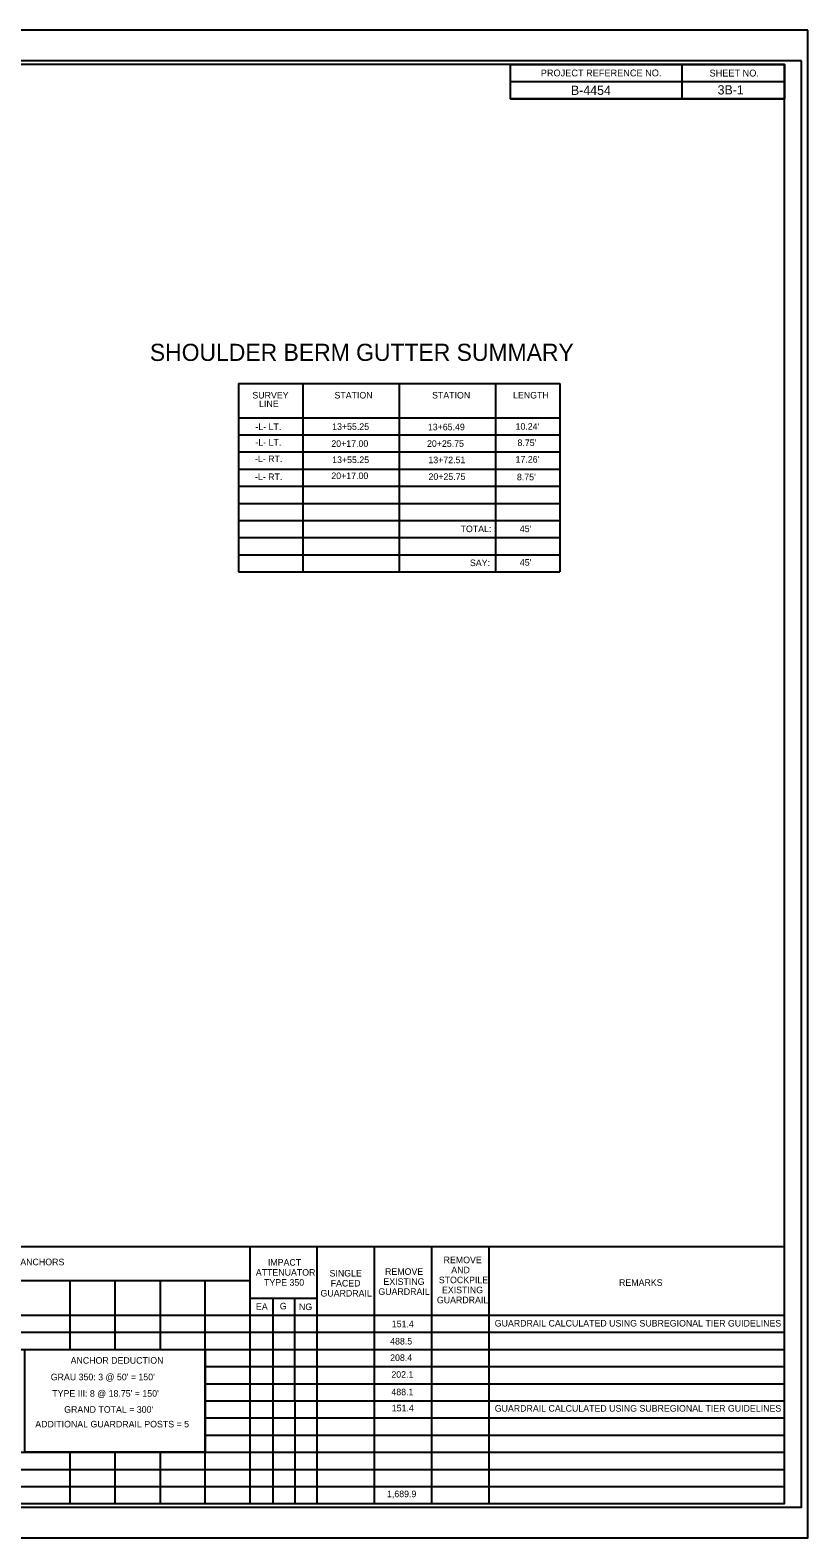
# Model space of a CAD drawing. Extents: x 1728103 to 1731948, y 539631 to 540733.
# Drawn here: x 1731380 to 1731948, y 539631 to 540731 of the extents above; entities that cross this region are included whole.
import ezdxf

# ---------------------------------------------------------------- set-up
doc = ezdxf.new("R2010")
doc.units = 0
for name, color, linetype in [('Sheet Cutting Line CELL', 7, 'Continuous'), ('Sheet Data Field CELL', 7, 'Continuous'), ('Sheet Plot Border Inside CELL', 7, 'Continuous'), ('Sheet Plot Border Outside CELL', 7, 'Continuous'), ('Sheet Summary Combination CELL', 7, 'Continuous'), ('Sheet Summary Combination Grid CELL', 7, 'Continuous')]:
    doc.layers.add(name, color=color, linetype=linetype)

msp = doc.modelspace()

# ---------------------------------------------------------------- linework, layer by layer
at = {"layer": 'Sheet Cutting Line CELL'}
for p, q in [((1731947.7, 540730.8), (1730263.7, 540730.8)), ((1730263.7, 539630.8), (1731947.7, 539630.8))]:
    msp.add_line(p, q, dxfattribs=at)
at = {"layer": 'Sheet Plot Border Inside CELL'}
msp.add_lwpolyline([(1731943.2, 540708.4), (1730276.7, 540708.4), (1730276.7, 539653.3), (1731943.2, 539653.3)], close=True, dxfattribs=at)
at = {"layer": 'Sheet Plot Border Outside CELL'}
msp.add_lwpolyline([(1731947.7, 540730.8), (1730263.7, 540730.8), (1730263.7, 539630.8), (1731947.7, 539630.8)], close=True, dxfattribs=at)
at = {"layer": 'Sheet Summary Combination CELL'}
for p, q in [((1731855.7, 540705.8), (1731855.7, 540680.8)), ((1731730.7, 540693.3), (1731930.7, 540693.3)), ((1731730.7, 540680.8), (1731930.7, 540680.8)), ((1731673.6, 540473.1), (1731673.6, 540473.1)), ((1731679.9, 540473), (1731679.9, 540473)), ((1731688.9, 540473.2), (1731688.9, 540473.2)), ((1731694.5, 540473.1), (1731694.5, 540473.1))]:
    msp.add_line(p, q, dxfattribs=at)
for points in [[(1731930.7, 540705.8), (1730430.7, 540705.8), (1730430.7, 539655.8), (1731930.7, 539655.8)], [(1731730.7, 540705.8), (1731930.7, 540705.8), (1731930.7, 540680.8), (1731730.7, 540680.8)]]:
    msp.add_lwpolyline(points, close=True, dxfattribs=at)
at = {"layer": 'Sheet Summary Combination Grid CELL'}
for p, q in [((1731532.4, 540473.1), (1731766.8, 540473.1)), ((1731532.4, 540473.1), (1731532.4, 540335.6)), ((1731579.3, 540473.1), (1731579.3, 540335.6)), ((1731649.6, 540473.1), (1731649.6, 540335.6)), ((1731719.9, 540473.1), (1731719.9, 540335.6)), ((1731766.8, 540473.1), (1731766.8, 540335.6)), ((1731532.4, 540448.1), (1731766.8, 540448.1)), ((1731532.4, 540435.6), (1731766.8, 540435.6)), ((1731532.4, 540423.1), (1731766.8, 540423.1)), ((1731532.4, 540410.6), (1731766.8, 540410.6)), ((1731532.4, 540398.1), (1731766.8, 540398.1)), ((1731532.4, 540385.6), (1731766.8, 540385.6)), ((1731532.4, 540373.1), (1731766.8, 540373.1)), ((1731532.4, 540360.6), (1731766.8, 540360.6)), ((1731532.4, 540348.1), (1731766.8, 540348.1)), ((1731532.4, 540335.6), (1731766.8, 540335.6)), ((1730430.7, 539843.3), (1731930.7, 539843.3)), ((1731540.7, 539843.3), (1731540.7, 539655.8)), ((1731589.5, 539843.3), (1731589.5, 539655.8)), ((1731631.3, 539843.3), (1731631.3, 539655.8)), ((1731673.1, 539843.3), (1731673.1, 539655.8)), ((1731715, 539843.3), (1731715, 539655.8)), ((1731540.7, 539818.3), (1731063.5, 539818.3)), ((1731409.4, 539818.3), (1731409.4, 539768.3)), ((1731442.2, 539818.3), (1731442.2, 539768.3)), ((1731475.1, 539818.3), (1731475.1, 539768.3)), ((1731507.9, 539818.3), (1731507.9, 539655.8)), ((1731540.7, 539805.6), (1731589.3, 539805.6)), ((1731557.3, 539805.6), (1731557.4, 539655.8)), ((1731573.3, 539805.6), (1731573.4, 539655.8)), ((1730430.7, 539793.3), (1731930.7, 539793.3)), ((1730430.7, 539780.8), (1731930.7, 539780.8)), ((1730430.7, 539768.3), (1731930.7, 539768.3)), ((1731507.9, 539755.8), (1731930.7, 539755.8)), ((1731507.9, 539743.3), (1731930.7, 539743.3)), ((1731507.9, 539730.8), (1731930.7, 539730.8)), ((1731507.9, 539718.3), (1731930.7, 539718.3)), ((1731507.9, 539705.8), (1731930.7, 539705.8)), ((1730430.7, 539693.3), (1731930.7, 539693.3)), ((1731409.4, 539693.3), (1731409.4, 539655.8)), ((1731442.2, 539693.3), (1731442.2, 539655.8)), ((1731475.1, 539693.3), (1731475.1, 539655.8)), ((1730430.7, 539680.8), (1731930.7, 539680.8)), ((1730430.7, 539668.3), (1731930.7, 539668.3))]:
    msp.add_line(p, q, dxfattribs=at)
msp.add_lwpolyline([(1731376.6, 539768.3), (1731508, 539768.3), (1731508, 539693.3), (1731376.6, 539693.3)], close=True, dxfattribs=at)

# ---------------------------------------------------------------- texts
at = {"layer": 'Sheet Data Field CELL'}
for s, p in [('B-4454', (1731774.9, 540683.6)), ('3B-1', (1731881.9, 540683.9))]:
    msp.add_text(s, height=6.75, dxfattribs=at).set_placement(p)
at = {"layer": 'Sheet Summary Combination CELL'}
for s, height, p in [('PROJECT REFERENCE NO.', 5, (1731752.9, 540697.1)), ('SHEET NO.', 5, (1731876, 540697)), ('SURVEY', 4.8, (1731542.5, 540462.1)), ('STATION', 4.8, (1731602.4, 540462.1)), ('STATION', 4.8, (1731673.6, 540462.1)), ('LENGTH', 4.8, (1731732.7, 540462.1)), ('LINE', 4.8, (1731547.4, 540455.8)), ('-L- LT.', 4.8, (1731544.7, 540439.1)), ('13+55.25', 4.8, (1731600.7, 540439.2)), ('13+65.49', 4.8, (1731670.5, 540438.9)), ("10.24'", 4.8, (1731734.5, 540439.3)), ('-L- LT.', 4.8, (1731544.7, 540427.7)), ('20+17.00', 4.8, (1731600.1, 540426.8)), ('20+25.75', 4.8, (1731669.9, 540426.8)), ("8.75'", 4.8, (1731735.9, 540427.4)), ('-L- RT.', 4.8, (1731544.4, 540415.7)), ('13+55.25', 4.8, (1731600.7, 540415)), ('13+72.51', 4.8, (1731670.9, 540414.9)), ("17.26'", 4.8, (1731734.5, 540415.3)), ('20+17.00', 4.8, (1731600.1, 540403.3)), ('-L- RT.', 4.8, (1731544.4, 540402.6)), ('20+25.75', 4.8, (1731671, 540402.7)), ("8.75'", 4.8, (1731735.5, 540402.4)), ('TOTAL:', 4.8, (1731694.4, 540364.6)), ("45'", 4.8, (1731737.6, 540364.6)), ('SAY:', 4.8, (1731701.2, 540339.8)), ("45'", 4.8, (1731737.6, 540340.1)), ('REMOVE', 4.8, (1731682, 539831.2)), ('ANCHORS', 4.8, (1731373.2, 539829.7)), ('ATTENUATOR', 4.8, (1731545, 539822.1)), ('IMPACT', 4.8, (1731553.8, 539829.4)), ('SINGLE', 4.8, (1731598.8, 539821.5)), ('REMOVE', 4.8, (1731639.3, 539822.7)), ('AND', 4.8, (1731687.6, 539823.9)), ('TYPE 350', 4.8, (1731551, 539814.8)), ('FACED', 4.8, (1731599.6, 539814.2)), ('EXISTING', 4.8, (1731638.1, 539815.4)), ('STOCKPILE', 4.8, (1731678.5, 539816.6)), ('EXISTING', 4.8, (1731680.8, 539809.3)), ('REMARKS', 4.8, (1731810, 539814.7)), ('GUARDRAIL', 4.8, (1731592.2, 539806.9)), ('GUARDRAIL', 4.8, (1731634.4, 539808.1)), ('GUARDRAIL', 4.8, (1731677.1, 539802)), ('EA', 4.8, (1731545.1, 539797.2)), ('G', 4.8, (1731562.5, 539797.5)), ('NG', 4.8, (1731576.5, 539797)), ('151.4', 4.8, (1731644.2, 539784.5)), ('GUARDRAIL CALCULATED USING SUBREGIONAL TIER GUIDELINES', 4.8, (1731719.3, 539785)), ('488.5', 4.8, (1731643, 539771.9)), ('ANCHOR DEDUCTION', 4.8, (1731409.9, 539757.9)), ('208.4', 4.8, (1731643, 539759.9)), ("GRAU 350: 3 @ 50' = 150'", 4.8, (1731395.4, 539745.8)), ('202.1', 4.8, (1731643.9, 539747.6)), ("TYPE III: 8 @ 18.75' = 150'", 4.8, (1731396.5, 539733.8)), ('488.1', 4.8, (1731643.9, 539734.9)), ("GRAND TOTAL = 300'", 4.8, (1731405.2, 539722.1)), ('151.4', 4.8, (1731644.2, 539723.1)), ('GUARDRAIL CALCULATED USING SUBREGIONAL TIER GUIDELINES', 4.8, (1731719.3, 539722.9)), ('ADDITIONAL GUARDRAIL POSTS = 5', 4.8, (1731384.1, 539711.4)), ('1,689.9', 4.8, (1731640.7, 539660.5))]:
    msp.add_text(s, height=height, dxfattribs=at).set_placement(p)
msp.add_text('SHOULDER BERM GUTTER SUMMARY', height=12.5, rotation=0.0119, dxfattribs=at).set_placement((1731467.7, 540489.5))

doc.saveas('drawing.dxf')
